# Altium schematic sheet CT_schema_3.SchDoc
size 294 x 169 mm
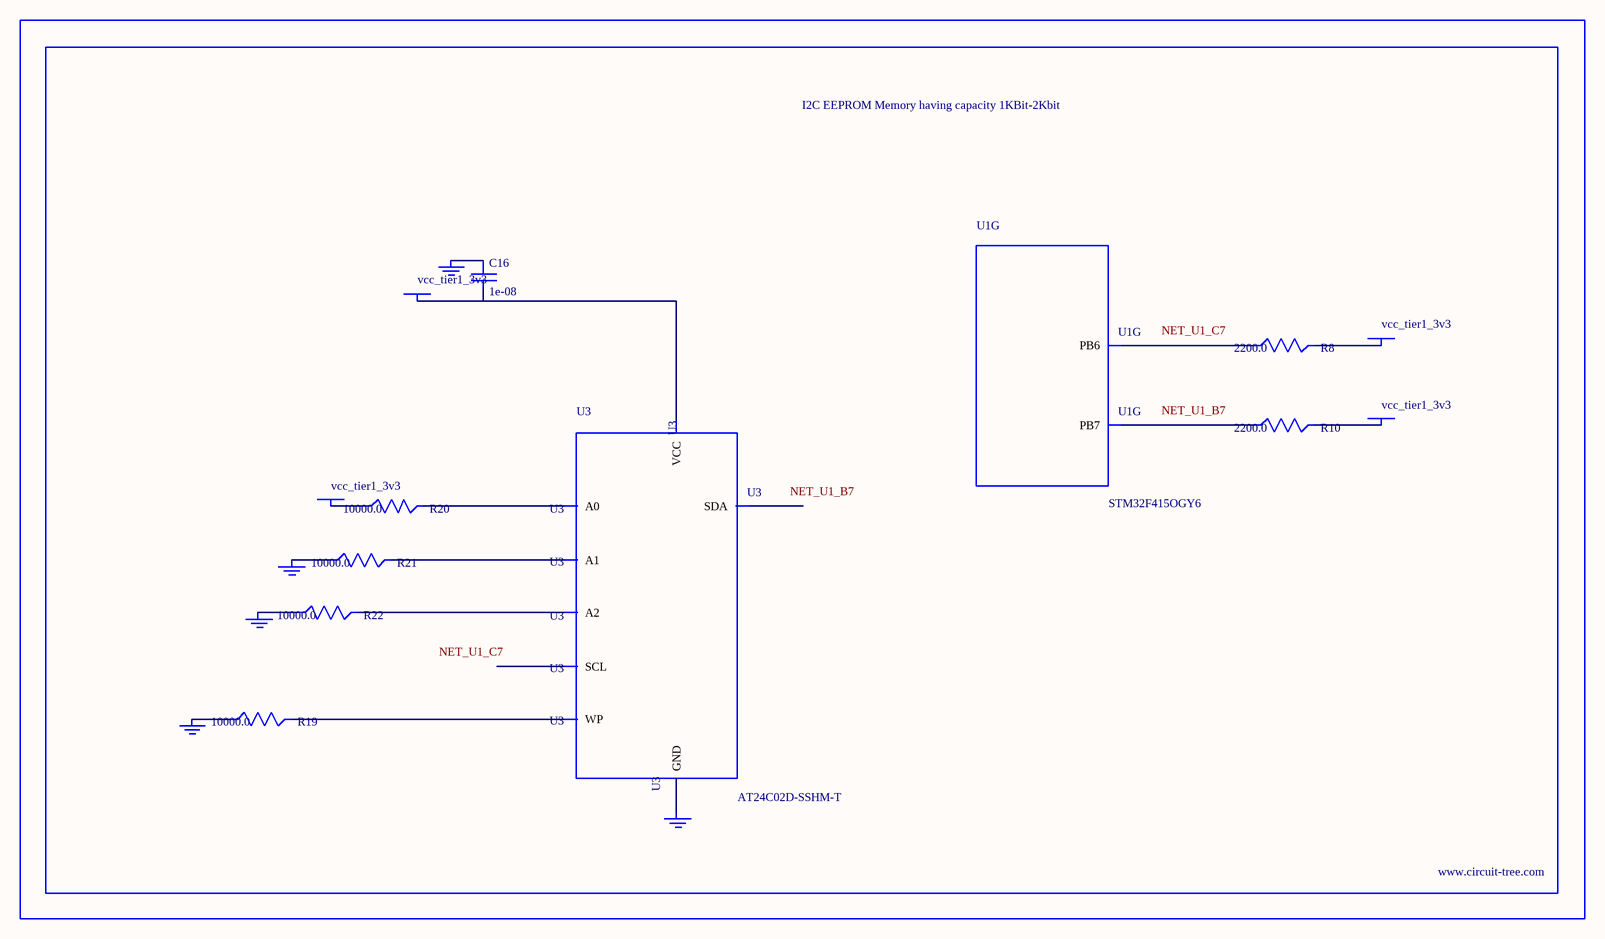
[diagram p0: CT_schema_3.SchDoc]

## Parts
BORDER2  (no value)
C16  1e-08  [C0402]
GND_INSTANCE_2_0  (no value)
GND_INSTANCE_2_1  (no value)
GND_INSTANCE_2_2  (no value)
GND_INSTANCE_2_3  (no value)
GND_INSTANCE_2_4  (no value)
POWER_INSTANCE_2_0  vcc_tier1_3v3
POWER_INSTANCE_2_1  vcc_tier1_3v3
POWER_INSTANCE_2_2  vcc_tier1_3v3
POWER_INSTANCE_2_3  vcc_tier1_3v3
R8  2200.0  [R0603]
R10  2200.0  [R0603]
R19  10000.0  [R0603]
R20  10000.0  [R0603]
R21  10000.0  [R0603]
R22  10000.0  [R0603]
U1  STM32F415OGY6  [WLCSP90]  (part G of 9)
U3  AT24C02D-SSHM-T  [AT24C02D]

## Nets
NetC16_1: C16.1 GND_INSTANCE_2_3.0(GND)
NetC16_2: C16.2 POWER_INSTANCE_2_1.0(PWR) U3.8(VCC)
NetGND_INSTANCE_2_0_0: GND_INSTANCE_2_0.0(GND) R21.1
NetGND_INSTANCE_2_1_0: GND_INSTANCE_2_1.0(GND) R22.1
NetGND_INSTANCE_2_2_0: GND_INSTANCE_2_2.0(GND) R19.1
NetGND_INSTANCE_2_4_0: GND_INSTANCE_2_4.0(GND) U3.4(GND)
NetPOWER_INSTANCE_2_0_0: POWER_INSTANCE_2_0.0(PWR) R20.1
NetPOWER_INSTANCE_2_2_0: POWER_INSTANCE_2_2.0(PWR) R8.2
NetPOWER_INSTANCE_2_3_0: POWER_INSTANCE_2_3.0(PWR) R10.2
NetR8_1: R8.1 U1.C7(PB6)
NetR10_1: R10.1 U1.B7(PB7)
NetR19_2: R19.2 U3.7(WP)
NetR20_2: R20.2 U3.1(A0)
NetR21_2: R21.2 U3.2(A1)
NetR22_2: R22.2 U3.3(A2)

Not connected (* = marked no-connect by the designer): U3 5(SDA) 6(SCL)

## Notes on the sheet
- Labels drawn without touching a wire or pin: NET_U1_B7, NET_U1_C7

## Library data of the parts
BORDER2 = BORDER_PAGE2
C16 = C0402C103K3RAC
GND_INSTANCE_2_0-GND_INSTANCE_2_4 = GND
POWER_INSTANCE_2_0-POWER_INSTANCE_2_3 = PWR
R8 R10 = RC0603JR-072K2L
R19-R22 = RC0603JR-0710KL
